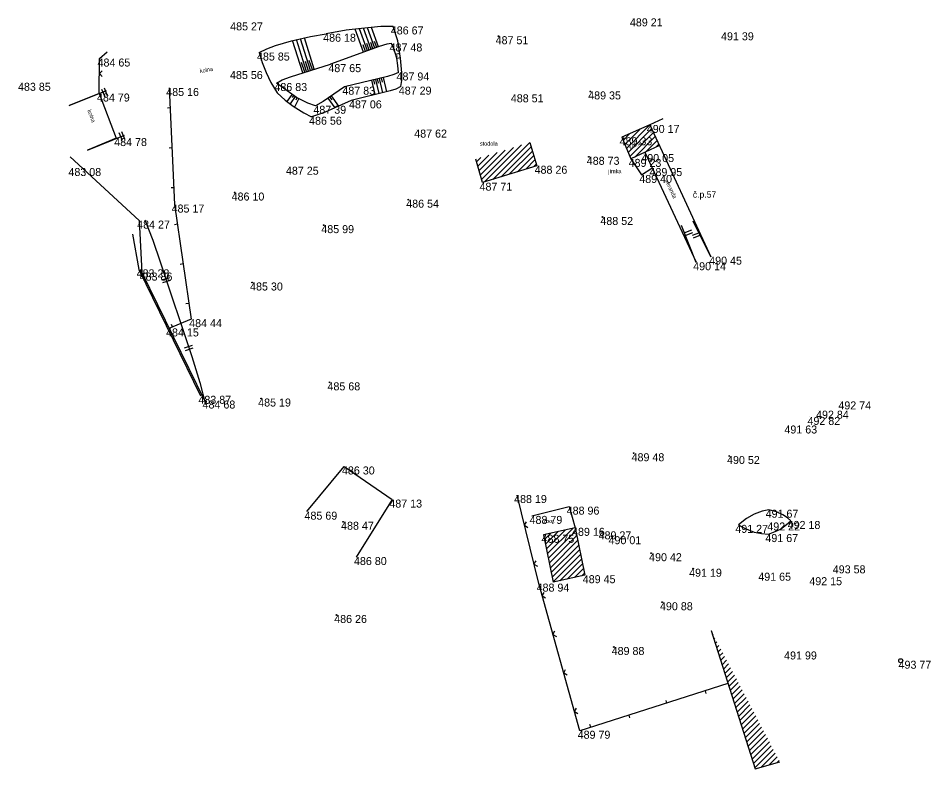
# Model space of a CAD drawing. Extents: x -553666 to -553461, y -1076543 to -1076230.
# Drawn here: x -553581.8 to -553467.8, y -1076463.6 to -1076369.8 of the extents above; entities that cross this region are included whole.
import ezdxf

# ---------------------------------------------------------------- set-up
doc = ezdxf.new("R2010")
doc.units = 0
for name, color, linetype in [('1', 7, 'Continuous'), ('12', 7, 'Continuous'), ('14', 7, 'Continuous'), ('18', 7, 'Continuous'), ('26', 7, 'Continuous'), ('27', 7, 'Continuous'), ('28', 7, 'Continuous'), ('32', 7, 'Continuous'), ('52', 7, 'Continuous'), ('54', 7, 'Continuous'), ('6', 7, 'Continuous'), ('62', 7, 'Continuous')]:
    doc.layers.add(name, color=color, linetype=linetype)

# ---------------------------------------------------------------- blocks, each defined once
blk = doc.blocks.new('POINT_DISPLAY')
blk.add_line((0, 0), (0, 0))
blk = doc.blocks.new('T')
at = {"layer": '6'}
blk.add_circle((0, 0), 0.05, dxfattribs=at)
blk = doc.blocks.new('SV')
at = {"layer": '1'}
blk.add_circle((0, 0), 0.25, dxfattribs=at)
blk = doc.blocks.new('ROV')
at = {"layer": '62'}
for p, q in [((-0.348, -0.51), (-0.348, 0.51)), ((0, -0.51), (0, 0.51))]:
    blk.add_line(p, q, dxfattribs=at)

msp = doc.modelspace()

# ---------------------------------------------------------------- linework, layer by layer
at = {"layer": '12'}
for p, q in [((-553571.67, -1076374.85), (-553570.73, -1076374.01)), ((-553571.74, -1076379.22), (-553571.67, -1076374.85)), ((-553571.7, -1076376.72), (-553571.34, -1076376.37)), ((-553571.7, -1076376.72), (-553571.35, -1076377.08)), ((-553562.97, -1076378.53), (-553562.31, -1076393.1)), ((-553562.86, -1076381.03), (-553563.21, -1076381.04)), ((-553562.63, -1076386.02), (-553562.98, -1076386.04)), ((-553562.4, -1076391.02), (-553562.75, -1076391.03)), ((-553562.31, -1076393.1), (-553560.25, -1076407.42)), ((-553561.95, -1076395.57), (-553562.3, -1076395.62)), ((-553561.24, -1076400.52), (-553561.59, -1076400.57)), ((-553560.53, -1076405.47), (-553560.88, -1076405.52)), ((-553560.25, -1076407.42), (-553563.01, -1076408.58)), ((-553562.56, -1076408.39), (-553562.69, -1076408.07)), ((-553516.81, -1076440.47), (-553519.5, -1076429.4)), ((-553518.58, -1076433.18), (-553518.32, -1076432.76)), ((-553518.58, -1076433.18), (-553518.15, -1076433.44)), ((-553517.4, -1076438.04), (-553517.14, -1076437.61)), ((-553517.4, -1076438.04), (-553516.97, -1076438.3)), ((-553511.66, -1076458.86), (-553516.81, -1076440.47)), ((-553516.38, -1076442.01), (-553516.13, -1076441.57)), ((-553516.38, -1076442.01), (-553515.94, -1076442.25)), ((-553515.03, -1076446.82), (-553514.79, -1076446.39)), ((-553515.03, -1076446.82), (-553514.59, -1076447.07)), ((-553513.68, -1076451.64), (-553513.44, -1076451.2)), ((-553513.68, -1076451.64), (-553513.25, -1076451.88)), ((-553493.16, -1076452.97), (-553511.66, -1076458.86)), ((-553496.01, -1076453.88), (-553495.91, -1076454.22)), ((-553500.78, -1076455.4), (-553500.89, -1076455.06)), ((-553512.33, -1076456.45), (-553512.09, -1076456.02)), ((-553512.33, -1076456.45), (-553511.9, -1076456.7)), ((-553505.54, -1076456.91), (-553505.44, -1076457.25)), ((-553510.31, -1076458.43), (-553510.41, -1076458.1))]:
    msp.add_line(p, q, dxfattribs=at)
at = {"layer": '14'}
for p, q in [((-553571.74, -1076379.22), (-553575.46, -1076380.74)), ((-553571.74, -1076379.22), (-553569.6, -1076384.79)), ((-553501.29, -1076382.4), (-553502.92, -1076383.15)), ((-553502.92, -1076383.15), (-553506.43, -1076384.69)), ((-553502.92, -1076383.15), (-553495.3, -1076399.64)), ((-553506.43, -1076384.69), (-553505.3, -1076387.39)), ((-553569.6, -1076384.79), (-553573.19, -1076386.3)), ((-553517.92, -1076385.34), (-553517.05, -1076388.25)), ((-553501.72, -1076385.72), (-553505.3, -1076387.39)), ((-553503.54, -1076386.57), (-553497.13, -1076400.31)), ((-553523.83, -1076390.36), (-553524.66, -1076387.42)), ((-553517.05, -1076388.25), (-553523.83, -1076390.36)), ((-553512.25, -1076433.5), (-553516.19, -1076434.37)), ((-553512.25, -1076433.5), (-553511.04, -1076439.42)), ((-553516.19, -1076434.37), (-553514.98, -1076440.29)), ((-553511.04, -1076439.42), (-553514.98, -1076440.29)), ((-553495.27, -1076446.33), (-553489.77, -1076463.61)), ((-553489.77, -1076463.61), (-553486.69, -1076462.73))]:
    msp.add_line(p, q, dxfattribs=at)
at = {"layer": '18'}
for p, q in [((-553505.3, -1076387.39), (-553503.98, -1076389.4)), ((-553503.98, -1076389.4), (-553502.67, -1076388.54)), ((-553517.68, -1076432.01), (-553513.02, -1076430.85)), ((-553513.02, -1076430.85), (-553512.25, -1076433.5))]:
    msp.add_line(p, q, dxfattribs=at)
at = {"layer": '26'}
for p, q in [((-553537.75, -1076373.72), (-553538.71, -1076371.06)), ((-553537.28, -1076373.56), (-553538.2, -1076371.02)), ((-553536.81, -1076373.39), (-553537.68, -1076370.97)), ((-553538.69, -1076374.06), (-553539.73, -1076371.18)), ((-553538.22, -1076373.89), (-553539.22, -1076371.12)), ((-553546.29, -1076376.64), (-553547.56, -1076372.59)), ((-553545.81, -1076376.49), (-553547.07, -1076372.48)), ((-553545.33, -1076376.34), (-553546.58, -1076372.37)), ((-553544.86, -1076376.19), (-553546.09, -1076372.26)), ((-553538.46, -1076373.98), (-553538.76, -1076373.13)), ((-553537.99, -1076373.81), (-553538.28, -1076372.99)), ((-553537.52, -1076373.64), (-553537.8, -1076372.86)), ((-553537.05, -1076373.47), (-553537.32, -1076372.73)), ((-553534.69, -1076374.32), (-553534.16, -1076374.17)), ((-553546.05, -1076376.56), (-553546.43, -1076375.36)), ((-553545.57, -1076376.41), (-553545.95, -1076375.22)), ((-553545.09, -1076376.26), (-553545.47, -1076375.08)), ((-553534.62, -1076374.56), (-553534.47, -1076374.52)), ((-553534.55, -1076374.8), (-553534.08, -1076374.72)), ((-553537.71, -1076377.57), (-553537.29, -1076379.36)), ((-553537.47, -1076377.51), (-553537.34, -1076378.05)), ((-553537.22, -1076377.45), (-553536.8, -1076379.24)), ((-553536.98, -1076377.4), (-553536.85, -1076377.93)), ((-553536.74, -1076377.34), (-553536.31, -1076379.12)), ((-553536.49, -1076377.28), (-553536.37, -1076377.81)), ((-553536.25, -1076377.22), (-553535.83, -1076379)), ((-553547.63, -1076379.32), (-553548.28, -1076380.2)), ((-553547.23, -1076379.61), (-553547.88, -1076380.5)), ((-553547.43, -1076379.46), (-553547.62, -1076379.73)), ((-553546.8, -1076379.86), (-553547.32, -1076380.91)), ((-553547.02, -1076379.75), (-553547.17, -1076380.06)), ((-553543.14, -1076379.79), (-553542.29, -1076381.01)), ((-553542.93, -1076379.65), (-553542.67, -1076380.03)), ((-553542.73, -1076379.51), (-553541.83, -1076380.8))]:
    msp.add_line(p, q, dxfattribs=at)
at = {"layer": '27'}
for p, q in [((-553566.73, -1076395.1), (-553575.34, -1076387.14)), ((-553566.73, -1076395.1), (-553566.4, -1076401.6)), ((-553566.4, -1076401.6), (-553558.55, -1076417.59)), ((-553545.78, -1076431.48), (-553541.11, -1076425.83)), ((-553541.11, -1076425.83), (-553535.1, -1076429.97)), ((-553535.1, -1076429.97), (-553539.61, -1076437.15))]:
    msp.add_line(p, q, dxfattribs=at)
for points in [[(-553535.01, -1076370.84), (-553536.52, -1076370.86), (-553538.97, -1076371.09), (-553540.88, -1076371.32), (-553543.36, -1076371.75)], [(-553534.02, -1076378.36), (-553533.93, -1076377.58), (-553533.93, -1076376.63), (-553534.06, -1076374.8), (-553534.41, -1076372.64), (-553535.01, -1076370.84)], [(-553551.75, -1076374.1), (-553550.77, -1076373.65), (-553549.68, -1076373.23), (-553547.71, -1076372.62), (-553545.32, -1076372.09), (-553543.36, -1076371.75)], [(-553535.19, -1076372.97), (-553535.8, -1076373.07), (-553536.74, -1076373.36), (-553542.82, -1076375.55)], [(-553534.31, -1076376.59), (-553534.39, -1076375.73), (-553534.55, -1076374.79), (-553534.85, -1076373.72), (-553535.19, -1076372.97)], [(-553551.75, -1076374.1), (-553551.36, -1076375.36), (-553550.87, -1076376.59), (-553550.27, -1076377.86), (-553549.49, -1076379.12), (-553548.48, -1076380.04), (-553547.49, -1076380.8), (-553546.17, -1076381.62), (-553545.21, -1076382.12)], [(-553549.56, -1076377.91), (-553548.86, -1076377.53), (-553547.84, -1076377.13), (-553542.82, -1076375.55)], [(-553534.31, -1076376.59), (-553534.92, -1076376.86), (-553535.71, -1076377.09), (-553541.08, -1076378.37)], [(-553544.69, -1076380.75), (-553545.65, -1076380.43), (-553547.06, -1076379.73), (-553549.56, -1076377.91)], [(-553541.08, -1076378.37), (-553543.73, -1076380.2), (-553544.69, -1076380.75)], [(-553534.02, -1076378.36), (-553534.65, -1076378.67), (-553535.38, -1076378.89), (-553540.24, -1076380.08)], [(-553540.24, -1076380.08), (-553543.47, -1076381.55), (-553544.19, -1076381.82), (-553545.21, -1076382.12)], [(-553488.06, -1076431.24), (-553488.87, -1076431.4), (-553489.9, -1076431.79), (-553490.85, -1076432.33), (-553491.86, -1076433.13)], [(-553485.32, -1076432.64), (-553485.71, -1076432.27), (-553486.31, -1076431.87), (-553487.09, -1076431.5), (-553488.06, -1076431.24)], [(-553488.09, -1076434.28), (-553487.25, -1076433.95), (-553486.61, -1076433.65), (-553485.83, -1076433.1), (-553485.32, -1076432.64)], [(-553491.86, -1076433.13), (-553491.08, -1076433.56), (-553489.87, -1076434.03), (-553488.95, -1076434.22), (-553488.09, -1076434.28)]]:
    msp.add_lwpolyline(points, dxfattribs=at)
at = {"layer": '28'}
for p, q in [((-553567.58, -1076396.8), (-553566.79, -1076401.2)), ((-553566.79, -1076401.2), (-553559.07, -1076417))]:
    msp.add_line(p, q, dxfattribs=at)
at = {"layer": '32'}
for p, q in [((-553505.85, -1076386.08), (-553502.92, -1076383.15)), ((-553506.27, -1076385.08), (-553505.44, -1076384.26)), ((-553506.06, -1076385.58), (-553504.18, -1076383.7)), ((-553505.64, -1076386.58), (-553502.7, -1076383.63)), ((-553505.43, -1076387.08), (-553502.47, -1076384.11)), ((-553504.81, -1076387.16), (-553502.24, -1076384.6)), ((-553523.56, -1076390.28), (-553518.94, -1076385.65)), ((-553522.54, -1076389.96), (-553517.92, -1076385.34)), ((-553521.51, -1076389.64), (-553517.75, -1076385.88)), ((-553503.48, -1076386.54), (-553502.02, -1076385.08)), ((-553502.16, -1076385.92), (-553501.8, -1076385.56)), ((-553524.41, -1076388.3), (-553523.03, -1076386.92)), ((-553524.25, -1076388.85), (-553522.01, -1076386.6)), ((-553524.1, -1076389.4), (-553520.98, -1076386.29)), ((-553523.94, -1076389.95), (-553519.96, -1076385.97)), ((-553520.48, -1076389.32), (-553517.59, -1076386.43)), ((-553519.46, -1076389), (-553517.43, -1076386.97)), ((-553524.57, -1076387.74), (-553524.05, -1076387.23)), ((-553518.43, -1076388.68), (-553517.27, -1076387.52)), ((-553517.4, -1076388.36), (-553517.11, -1076388.06)), ((-553515.83, -1076436.13), (-553513.47, -1076433.77)), ((-553515.71, -1076436.72), (-553512.56, -1076433.57)), ((-553516.07, -1076434.96), (-553515.28, -1076434.17)), ((-553515.95, -1076435.54), (-553514.38, -1076433.97)), ((-553515.59, -1076437.31), (-553512.17, -1076433.89)), ((-553515.47, -1076437.89), (-553512.05, -1076434.47)), ((-553515.35, -1076438.48), (-553511.93, -1076435.06)), ((-553515.23, -1076439.07), (-553511.81, -1076435.65)), ((-553515.11, -1076439.65), (-553511.69, -1076436.24)), ((-553514.99, -1076440.24), (-553511.57, -1076436.82)), ((-553514.15, -1076440.11), (-553511.45, -1076437.41)), ((-553513.24, -1076439.91), (-553511.33, -1076438)), ((-553512.33, -1076439.71), (-553511.21, -1076438.58)), ((-553511.43, -1076439.51), (-553511.09, -1076439.17)), ((-553495.1, -1076446.87), (-553495.02, -1076446.8)), ((-553494.93, -1076447.41), (-553494.78, -1076447.26)), ((-553494.76, -1076447.94), (-553494.54, -1076447.73)), ((-553494.58, -1076448.48), (-553494.3, -1076448.19)), ((-553494.41, -1076449.02), (-553494.05, -1076448.66)), ((-553494.24, -1076449.55), (-553493.81, -1076449.12)), ((-553494.07, -1076450.09), (-553493.57, -1076449.58)), ((-553493.9, -1076450.63), (-553493.33, -1076450.05)), ((-553493.73, -1076451.16), (-553493.08, -1076450.51)), ((-553493.56, -1076451.7), (-553492.84, -1076450.98)), ((-553493.39, -1076452.24), (-553492.6, -1076451.44)), ((-553493.22, -1076452.77), (-553492.35, -1076451.91)), ((-553493.05, -1076453.31), (-553492.11, -1076452.37)), ((-553492.88, -1076453.84), (-553491.87, -1076452.83)), ((-553492.71, -1076454.38), (-553491.62, -1076453.3)), ((-553492.54, -1076454.92), (-553491.38, -1076453.76)), ((-553492.36, -1076455.45), (-553491.14, -1076454.23)), ((-553492.2, -1076455.99), (-553490.9, -1076454.69)), ((-553492.02, -1076456.53), (-553490.65, -1076455.16)), ((-553491.85, -1076457.06), (-553490.41, -1076455.62)), ((-553491.68, -1076457.6), (-553490.17, -1076456.09)), ((-553491.51, -1076458.14), (-553489.93, -1076456.55)), ((-553491.34, -1076458.67), (-553489.68, -1076457.01)), ((-553491.17, -1076459.21), (-553489.44, -1076457.48)), ((-553491, -1076459.75), (-553489.2, -1076457.94)), ((-553490.83, -1076460.28), (-553488.95, -1076458.41)), ((-553490.66, -1076460.82), (-553488.71, -1076458.87)), ((-553490.49, -1076461.35), (-553488.47, -1076459.34)), ((-553490.32, -1076461.89), (-553488.23, -1076459.8)), ((-553490.15, -1076462.43), (-553487.98, -1076460.26)), ((-553489.98, -1076462.96), (-553487.74, -1076460.73)), ((-553489.81, -1076463.5), (-553487.5, -1076461.19)), ((-553488.98, -1076463.39), (-553487.26, -1076461.66)), ((-553487.99, -1076463.1), (-553487.01, -1076462.12)), ((-553487.01, -1076462.82), (-553486.77, -1076462.59))]:
    msp.add_line(p, q, dxfattribs=at)
at = {"layer": '62'}
for p, q in [((-553575.46, -1076380.74), (-553570.83, -1076378.85)), ((-553573.19, -1076386.3), (-553568.56, -1076384.41)), ((-553566.02, -1076395), (-553565.04, -1076397.53)), ((-553497.14, -1076400.36), (-553498.96, -1076395.7)), ((-553495.3, -1076399.64), (-553497.51, -1076395.16)), ((-553565.04, -1076397.53), (-553564.1, -1076400.27)), ((-553564.1, -1076400.27), (-553560.16, -1076412.09)), ((-553560.16, -1076412.09), (-553559.17, -1076415.33)), ((-553559.17, -1076415.33), (-553558.45, -1076418.09))]:
    msp.add_line(p, q, dxfattribs=at)

# ---------------------------------------------------------------- block references
at = {"layer": '1'}
for name, p in [('POINT_DISPLAY', (-553505.03, -1076369.83)), ('POINT_DISPLAY', (-553555.1, -1076370.33)), ('POINT_DISPLAY', (-553535.01, -1076370.84)), ('POINT_DISPLAY', (-553543.36, -1076371.75)), ('POINT_DISPLAY', (-553521.82, -1076372.06)), ('POINT_DISPLAY', (-553493.63, -1076371.57)), ('POINT_DISPLAY', (-553535.19, -1076372.97)), ('POINT_DISPLAY', (-553551.75, -1076374.1)), ('POINT_DISPLAY', (-553571.67, -1076374.85)), ('POINT_DISPLAY', (-553542.82, -1076375.55)), ('POINT_DISPLAY', (-553555.11, -1076376.41)), ('POINT_DISPLAY', (-553553.58, -1076376.67)), ('POINT_DISPLAY', (-553534.31, -1076376.59)), ('POINT_DISPLAY', (-553581.61, -1076377.88)), ('POINT_DISPLAY', (-553549.56, -1076377.91)), ('POINT_DISPLAY', (-553562.97, -1076378.53)), ('POINT_DISPLAY', (-553541.08, -1076378.37)), ('POINT_DISPLAY', (-553534.02, -1076378.36)), ('POINT_DISPLAY', (-553510.35, -1076378.96)), ('POINT_DISPLAY', (-553571.74, -1076379.22)), ('POINT_DISPLAY', (-553540.24, -1076380.08)), ('POINT_DISPLAY', (-553519.92, -1076379.32)), ('POINT_DISPLAY', (-553544.69, -1076380.75)), ('POINT_DISPLAY', (-553545.21, -1076382.12)), ('POINT_DISPLAY', (-553502.92, -1076383.15)), ('POINT_DISPLAY', (-553532.09, -1076383.73)), ('POINT_DISPLAY', (-553506.43, -1076384.69)), ('POINT_DISPLAY', (-553569.6, -1076384.79)), ('POINT_DISPLAY', (-553503.7, -1076386.79)), ('POINT_DISPLAY', (-553510.54, -1076387.13)), ('POINT_DISPLAY', (-553505.3, -1076387.39)), ('POINT_DISPLAY', (-553575.31, -1076388.53)), ('POINT_DISPLAY', (-553548.13, -1076388.37)), ('POINT_DISPLAY', (-553517.05, -1076388.25)), ('POINT_DISPLAY', (-553502.67, -1076388.54)), ('POINT_DISPLAY', (-553523.83, -1076390.36)), ('POINT_DISPLAY', (-553503.98, -1076389.4)), ('POINT_DISPLAY', (-553554.8, -1076391.6)), ('POINT_DISPLAY', (-553533.1, -1076392.49)), ('POINT_DISPLAY', (-553562.31, -1076393.1)), ('POINT_DISPLAY', (-553508.84, -1076394.65)), ('POINT_DISPLAY', (-553566.73, -1076395.1)), ('POINT_DISPLAY', (-553543.68, -1076395.67)), ('POINT_DISPLAY', (-553497.13, -1076400.31)), ('POINT_DISPLAY', (-553495.24, -1076399.61)), ('POINT_DISPLAY', (-553566.79, -1076401.2)), ('POINT_DISPLAY', (-553566.4, -1076401.6)), ('POINT_DISPLAY', (-553552.61, -1076402.84)), ('POINT_DISPLAY', (-553560.25, -1076407.42)), ('POINT_DISPLAY', (-553563.01, -1076408.58)), ('POINT_DISPLAY', (-553542.93, -1076415.32)), ('POINT_DISPLAY', (-553559.07, -1076417)), ('POINT_DISPLAY', (-553558.55, -1076417.59)), ('POINT_DISPLAY', (-553551.48, -1076417.34)), ('POINT_DISPLAY', (-553479.1, -1076417.7)), ('POINT_DISPLAY', (-553481.89, -1076418.86)), ('POINT_DISPLAY', (-553482.95, -1076419.64)), ('POINT_DISPLAY', (-553485.71, -1076420.71)), ('POINT_DISPLAY', (-553504.94, -1076424.18)), ('POINT_DISPLAY', (-553492.99, -1076424.52)), ('POINT_DISPLAY', (-553541.11, -1076425.83)), ('POINT_DISPLAY', (-553535.1, -1076429.97)), ('POINT_DISPLAY', (-553519.5, -1076429.4)), ('POINT_DISPLAY', (-553545.78, -1076431.48)), ('POINT_DISPLAY', (-553513.02, -1076430.85)), ('POINT_DISPLAY', (-553488.06, -1076431.24)), ('POINT_DISPLAY', (-553517.68, -1076432.01)), ('POINT_DISPLAY', (-553485.32, -1076432.64)), ('POINT_DISPLAY', (-553541.25, -1076432.74)), ('POINT_DISPLAY', (-553512.25, -1076433.5)), ('POINT_DISPLAY', (-553491.86, -1076433.13)), ('POINT_DISPLAY', (-553487.97, -1076432.83)), ('POINT_DISPLAY', (-553516.19, -1076434.37)), ('POINT_DISPLAY', (-553509.05, -1076433.94)), ('POINT_DISPLAY', (-553507.7, -1076434.55)), ('POINT_DISPLAY', (-553488.09, -1076434.28)), ('POINT_DISPLAY', (-553539.61, -1076437.15)), ('POINT_DISPLAY', (-553502.75, -1076436.67)), ('POINT_DISPLAY', (-553479.79, -1076438.19)), ('POINT_DISPLAY', (-553511.04, -1076439.42)), ('POINT_DISPLAY', (-553497.51, -1076438.61)), ('POINT_DISPLAY', (-553488.98, -1076439.11)), ('POINT_DISPLAY', (-553516.81, -1076440.47)), ('POINT_DISPLAY', (-553482.61, -1076439.67)), ('POINT_DISPLAY', (-553501.37, -1076442.8)), ('POINT_DISPLAY', (-553542.07, -1076444.39)), ('POINT_DISPLAY', (-553507.42, -1076448.39)), ('POINT_DISPLAY', (-553485.73, -1076448.95)), ('SV', (-553471.57, -1076450.11)), ('POINT_DISPLAY', (-553471.57, -1076450.11)), ('POINT_DISPLAY', (-553511.66, -1076458.86))]:
    msp.add_blockref(name, p, dxfattribs=at)
at = {"layer": '32'}
for p in [(-553502.92, -1076383.15), (-553517.92, -1076385.34), (-553516.19, -1076434.37), (-553495.27, -1076446.33)]:
    msp.add_blockref('POINT_DISPLAY', p, dxfattribs=at)
at = {"layer": '6'}
for p in [(-553521.82, -1076372.06), (-553510.35, -1076378.96), (-553510.54, -1076387.13), (-553554.8, -1076391.6), (-553533.1, -1076392.49), (-553508.84, -1076394.65), (-553543.68, -1076395.67), (-553552.61, -1076402.84), (-553542.93, -1076415.32), (-553551.48, -1076417.34), (-553504.94, -1076424.18), (-553492.99, -1076424.52), (-553541.25, -1076432.74), (-553509.05, -1076433.94), (-553507.7, -1076434.55), (-553502.75, -1076436.67), (-553497.51, -1076438.61), (-553501.37, -1076442.8), (-553542.07, -1076444.39), (-553507.42, -1076448.39)]:
    msp.add_blockref('T', p, dxfattribs=at)
at = {"layer": '62'}
for p, xscale, yscale, rotation in [((-553571.23, -1076379.13), 1.0000008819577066, 1.0000008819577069, -157.7900938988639), ((-553569.06, -1076384.56), 1.0000008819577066, 1.0000008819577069, -157.7900938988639), ((-553498.2, -1076396.49), 0.9999984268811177, 0.9999984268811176, 111.37150808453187), ((-553497.17, -1076396.8), 0.9999984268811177, 0.9999984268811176, 111.37150808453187), ((-553563.29, -1076402.69), 0.9999988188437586, 0.9999988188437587, -71.56791979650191), ((-553560.46, -1076411.18), 0.9999988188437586, 0.9999988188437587, -71.56791979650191)]:
    msp.add_blockref('ROV', p, dxfattribs=dict(at, xscale=xscale, yscale=yscale, rotation=rotation))

# ---------------------------------------------------------------- texts
at = {"layer": '52'}
for s, rotation, p in [('kolna', 9.758, (-553559.11, -1076376.66)), ('kolna', 291.0168, (-553573.22, -1076381.35)), ('kolna', 23.6893, (-553505.4, -1076386.21)), ('veranda', 295.0119, (-553501.03, -1076390.14))]:
    msp.add_text(s, height=0.5, rotation=rotation, dxfattribs=at).set_placement(p)
for s, p in [('stodola', (-553524.16, -1076385.73)), ('jímka', (-553508.11, -1076389.18)), ('zbor.', (-553516.23, -1076432.9))]:
    msp.add_text(s, height=0.5, dxfattribs=at).set_placement(p)
at = {"layer": '54'}
msp.add_text('č.p.57', height=0.8, dxfattribs=at).set_placement((-553497.54, -1076392.24))
at = {"layer": '6'}
for s, p in [('489 21 ', (-553505.41, -1076370.83)), ('485 27 ', (-553555.36, -1076371.33)), ('486 67 ', (-553535.29, -1076371.84)), ('486 18 ', (-553543.74, -1076372.75)), ('487 51 ', (-553522.19, -1076373.06)), ('491 39 ', (-553494.02, -1076372.57)), ('487 48 ', (-553535.44, -1076373.97)), ('485 85 ', (-553552.01, -1076375.1)), ('484 65 ', (-553571.93, -1076375.85)), ('487 65 ', (-553543.09, -1076376.55)), ('485 56 ', (-553555.38, -1076377.41)), ('487 94 ', (-553534.57, -1076377.59)), ('483 85 ', (-553581.87, -1076378.88)), ('486 83 ', (-553549.83, -1076378.91)), ('485 16 ', (-553563.35, -1076379.53)), ('487 83 ', (-553541.34, -1076379.37)), ('487 29 ', (-553534.29, -1076379.36)), ('489 35 ', (-553510.62, -1076379.96)), ('484 79 ', (-553572, -1076380.22)), ('487 06 ', (-553540.51, -1076381.08)), ('488 51 ', (-553520.29, -1076380.32)), ('487 39 ', (-553544.96, -1076381.75)), ('486 56 ', (-553545.5, -1076383.12)), ('490 17 ', (-553503.3, -1076384.15)), ('487 62 ', (-553532.36, -1076384.73)), ('489 33 ', (-553506.7, -1076385.69)), ('484 78 ', (-553569.85, -1076385.79)), ('490 05 ', (-553503.98, -1076387.79)), ('488 73 ', (-553510.8, -1076388.13)), ('489 23 ', (-553505.57, -1076388.39)), ('483 08 ', (-553575.57, -1076389.53)), ('487 25 ', (-553548.39, -1076389.37)), ('488 26 ', (-553517.32, -1076389.25)), ('489 95 ', (-553502.96, -1076389.54)), ('487 71 ', (-553524.2, -1076391.36)), ('489 40 ', (-553504.24, -1076390.4)), ('486 10 ', (-553555.18, -1076392.6)), ('486 54 ', (-553533.36, -1076393.49)), ('485 17 ', (-553562.68, -1076394.1)), ('488 52 ', (-553509.1, -1076395.65)), ('484 27 ', (-553566.98, -1076396.1)), ('485 99 ', (-553543.97, -1076396.67)), ('490 14 ', (-553497.5, -1076401.31)), ('490 45 ', (-553495.5, -1076400.61)), ('483 28 ', (-553567.05, -1076402.2)), ('483 86 ', (-553566.67, -1076402.6)), ('485 30 ', (-553552.87, -1076403.84)), ('484 44 ', (-553560.48, -1076408.42)), ('484 15 ', (-553563.37, -1076409.58)), ('485 68 ', (-553543.2, -1076416.32)), ('483 87 ', (-553559.33, -1076418)), ('484 68 ', (-553558.81, -1076418.59)), ('485 19 ', (-553551.86, -1076418.34)), ('492 74 ', (-553479.36, -1076418.7)), ('492 84 ', (-553482.15, -1076419.86)), ('492 82 ', (-553483.22, -1076420.64)), ('491 63 ', (-553486.1, -1076421.71)), ('489 48 ', (-553505.2, -1076425.18)), ('490 52 ', (-553493.27, -1076425.52)), ('486 30 ', (-553541.39, -1076426.83)), ('487 13 ', (-553535.47, -1076430.97)), ('488 19 ', (-553519.88, -1076430.4)), ('485 69 ', (-553546.07, -1076432.48)), ('488 96 ', (-553513.31, -1076431.85)), ('491 67 ', (-553488.45, -1076432.24)), ('488 79 ', (-553517.95, -1076433.01)), ('492 18 ', (-553485.7, -1076433.64)), ('488 47 ', (-553541.5, -1076433.74)), ('489 16 ', (-553512.64, -1076434.5)), ('491 27 ', (-553492.24, -1076434.13)), ('492 22 ', (-553488.24, -1076433.83)), ('488 75 ', (-553516.45, -1076435.37)), ('489 27 ', (-553509.32, -1076434.94)), ('490 01 ', (-553508.08, -1076435.55)), ('491 67 ', (-553488.48, -1076435.28)), ('486 80 ', (-553539.89, -1076438.15)), ('490 42 ', (-553503.01, -1076437.67)), ('493 58 ', (-553480.06, -1076439.19)), ('489 45 ', (-553511.3, -1076440.42)), ('491 19 ', (-553498.01, -1076439.61)), ('491 65 ', (-553489.37, -1076440.11)), ('488 94 ', (-553517.07, -1076441.47)), ('492 15 ', (-553482.99, -1076440.67)), ('490 88 ', (-553501.65, -1076443.8)), ('486 26 ', (-553542.36, -1076445.39)), ('489 88 ', (-553507.69, -1076449.39)), ('491 99 ', (-553486.14, -1076449.95)), ('493 77 ', (-553471.84, -1076451.11)), ('489 79 ', (-553511.94, -1076459.86))]:
    msp.add_text(s, height=1, dxfattribs=at).set_placement(p)

doc.saveas('drawing.dxf')
